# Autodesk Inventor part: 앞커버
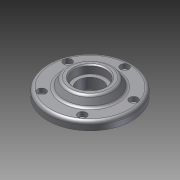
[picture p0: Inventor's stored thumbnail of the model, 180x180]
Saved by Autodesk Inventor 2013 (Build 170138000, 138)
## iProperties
Company: 한국ATC센터
Created: 2014-03
Part Number: 앞커버
Document SubType Name: Modeling
Designer: KYOUNG IL JANG
Density: 1 g/cm^3
Material: 일반
Author: KYOUNG IL JANG
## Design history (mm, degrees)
sketch "스케치1"
  geometry: C1 r 26 at (0, 0); C2 r 40 at (0, 0); 1 further point
  constraints: 2 centre point, 2 coincident
  dimensions: "d0" = 52 diameter of C1; "d1" = 80 diameter of C2
extrude "돌출1" new body sketch "스케치1" distance "d2" = 8; taper "d3" = 0 deg
extrude "돌출2" join sketch "스케치1" distance "d4" = 5; taper "d5" = 0 deg
sketch "스케치2"
  geometry: C1 r 25 at (0, 0); 1 further point
  constraints: 1 centre point, 1 coincident
  dimensions: "d6" = 50 diameter of C1
extrude "돌출3" join sketch "스케치2" distance "d7" = 8; taper "d8" = -30 deg
sketch "스케치3"
  geometry: C1 r 1.729 at (0, 33) reference; 1 further point
hole "구멍1" sketch "스케치3" at (0, 33) diameter "d9" = 4.5; stored, may be unused: countersink angle "d13" = 90 deg, drill point angle "d15" = 118 deg; dims "d10" = 6, "d11" = 8, "d12" = 4.4, "d14" = 8
hole "구멍2" diameter "d21" = 23; stored, may be unused: countersink angle "d25" = 90 deg, drill point angle "d27" = 118 deg; dims "d19" = 10, "d20" = 10, "d22" = 6, "d23" = 30, "d24" = 8, "d26" = 8
fillet "모깎기1" dims "d28" = 3, "d29" = 0.3
hole "구멍3" diameter "d32" = 40; stored, may be unused: countersink angle "d36" = 90 deg, drill point angle "d38" = 0 deg; dims "d30" = 10, "d31" = 10, "d33" = 6, "d34" = 30, "d35" = 8, "d37" = 3
fillet "모깎기2" dims "d39" = 3
chamfer "모따기1" distance "d40" = 1; stored, may be unused: second distance "d41" = 2, angle "d42" = 45 deg
node "솔리드1"
pattern_circular "원형 패턴1" dims angle "d17" = 360 deg
node "참조1"
